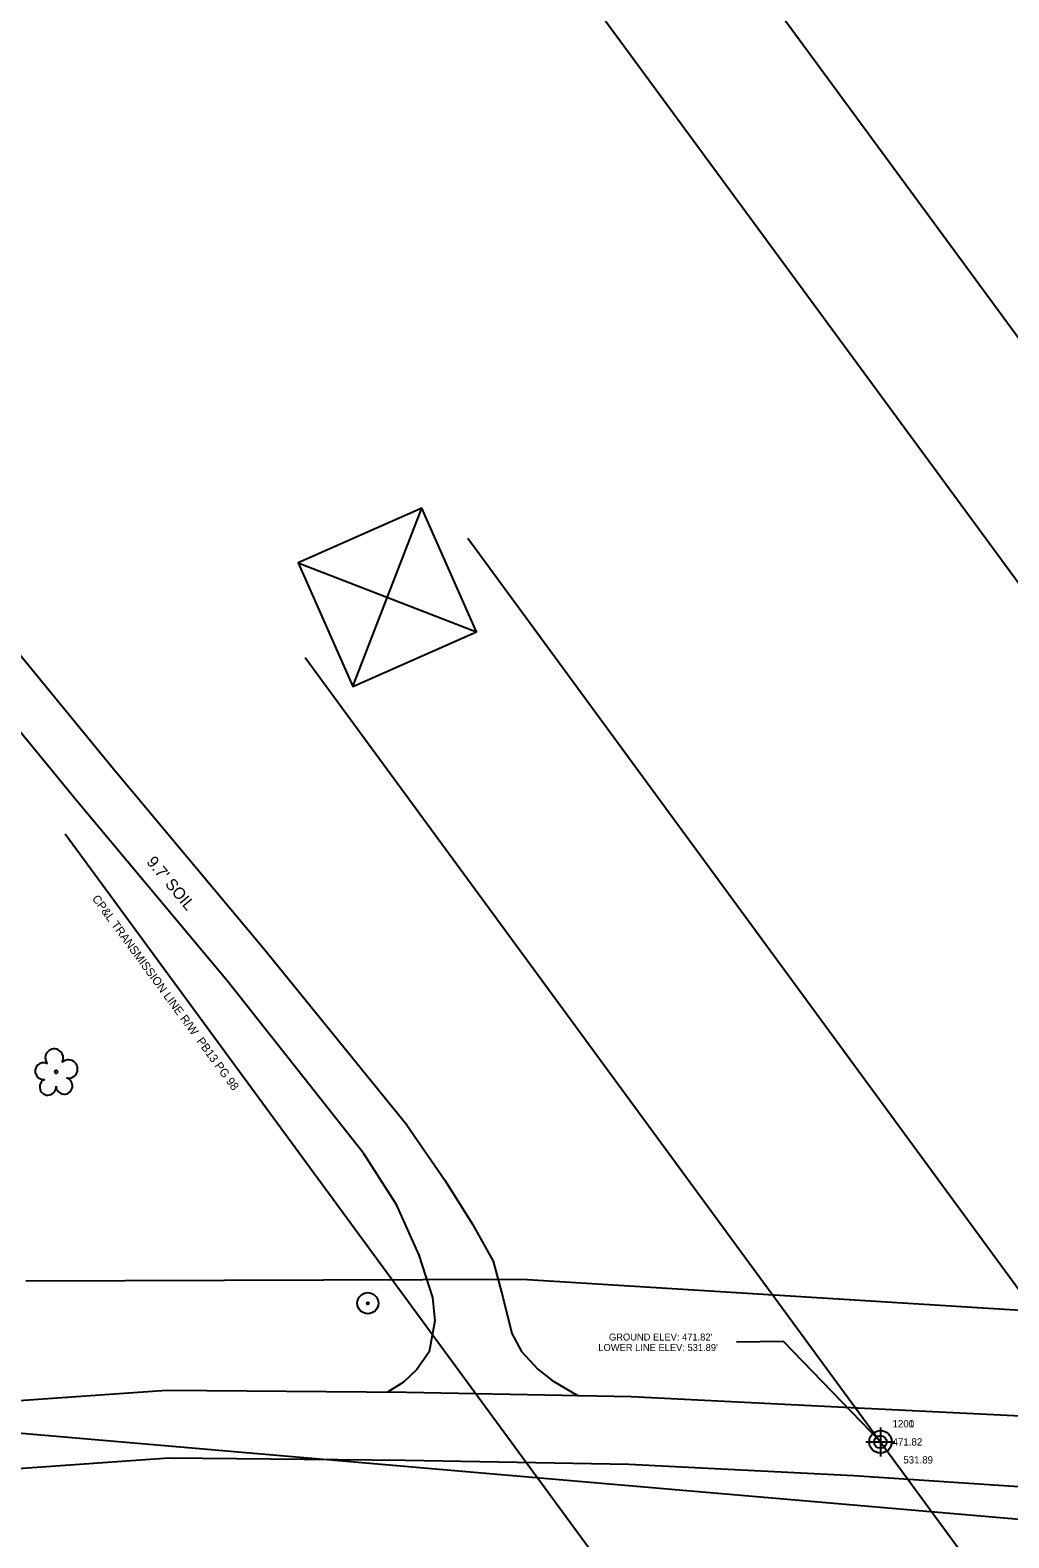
# Model space of a CAD drawing. Extents: x 2060057 to 2062431, y 911685 to 913703.
# Drawn here: x 2060635.5 to 2060837.6, y 912720.7 to 913031.9 of the extents above; entities that cross this region are included whole.
import ezdxf

# ---------------------------------------------------------------- set-up
doc = ezdxf.new("R2010")
doc.units = 0
for name, color, linetype in [('Cogo Default Point CELL', 7, 'Continuous'), ('COGO Default Point Elevation', 7, 'Continuous'), ('COGO Default Point Number', 7, 'Continuous'), ('Exist Horizontal Baseline Alignment', 7, 'Continuous'), ('Exist Right of Way Line', 7, 'Continuous'), ('Exist Right of Way Line Text', 7, 'Continuous'), ('Exist Roads Soil', 7, 'Continuous'), ('Exist Roads Soil Text', 7, 'Continuous'), ('Exist Utilities Other Located Object CELL', 7, 'Continuous'), ('Exist Utilities Other Located Object Leader', 7, 'Continuous'), ('Exist Utilities Other Located Object Text', 7, 'Continuous'), ('Exist Utilities Power Tower CELL', 7, 'Continuous'), ('Exist Utilities Power UG Cable', 7, 'Continuous'), ('Exist Vegetation Tree CELL', 7, 'Continuous')]:
    doc.layers.add(name, color=color, linetype=linetype)

# ---------------------------------------------------------------- blocks, each defined once
blk = doc.blocks.new('EXIST UTILITIES OTHER LOCATED OBJECT')
at = {"layer": 'Exist Utilities Other Located Object CELL'}
for radius in [0.0436, 0.0048]:
    blk.add_circle((0, 0), radius, dxfattribs=at)
blk = doc.blocks.new('EXIST VEGETATION TREE')
at = {"layer": 'Exist Vegetation Tree CELL'}
blk.add_line((0, 0), (0, 0), dxfattribs=at)
blk.add_circle((0, 0), 0.00652, dxfattribs=at)
for centre, radius, start, end in [((-0.0077, 0.0575), 0.0371, 330.16508, 219.71335), ((-0.0521, 0.0031), 0.0345, 62.66361, 279.3457), ((0.051, 0.0118), 0.038, 257.1011, 134.19993), ((-0.0341, -0.0624), 0.0338, 111.56708, 6.23104), ((0.0335, -0.058), 0.034, 181.28216, 74.55999)]:
    blk.add_arc(centre, radius, start, end, dxfattribs=at)

msp = doc.modelspace()

# ---------------------------------------------------------------- linework, layer by layer
at = {"layer": 'Cogo Default Point CELL'}
for points in [[(2060811.07, 912743.46), (2060811.07, 912740.46)], [(2060811.07, 912743.46), (2060811.07, 912740.46)], [(2060808.07, 912740.46), (2060811.07, 912740.46)], [(2060808.07, 912740.46), (2060811.07, 912740.46)], [(2060811.07, 912740.46), (2060814.07, 912740.46)], [(2060811.07, 912740.46), (2060811.07, 912737.46)], [(2060811.07, 912740.46), (2060814.07, 912740.46)], [(2060811.07, 912740.46), (2060811.07, 912737.46)]]:
    msp.add_lwpolyline(points, dxfattribs=at)
msp.add_circle((2060811.07, 912740.46), 2.34, dxfattribs=at)
msp.add_circle((2060811.07, 912740.46), 2.34, dxfattribs=at)
at = {"layer": 'Exist Horizontal Baseline Alignment'}
msp.add_lwpolyline([(2060519.43, 912752.09), (2061230.37, 912690.89), (2061909.97, 912640.52)], dxfattribs=at)
at = {"layer": 'Exist Right of Way Line'}
for p, q in [((2060737.08, 912774.01), (2060634.59, 912773.61)), ((2060840, 912767.59), (2060737.08, 912774.01))]:
    msp.add_line(p, q, dxfattribs=at)
msp.add_lwpolyline([(2060642.71, 912865.98), (2061240.84, 912050.99)], dxfattribs=at)
at = {"layer": 'Exist Roads Soil'}
for points in [[(2060713.36, 912805.74), (2060683.97, 912841.93), (2060652.7, 912879.29), (2060619.5, 912919.71), (2060595.31, 912948.3), (2060581.6, 912964.35), (2060565.45, 912981.01), (2060558.75, 912988.23)], [(2060704.23, 912800.14), (2060676.24, 912835.58), (2060645, 912872.9), (2060611.82, 912913.31), (2060587.69, 912941.82), (2060574.2, 912957.62), (2060558.36, 912973.95), (2060550.71, 912981.07)], [(2060713.36, 912805.74), (2060721.1, 912794.45), (2060726.86, 912785.4), (2060731.09, 912777.77), (2060733.12, 912770.33), (2060734.96, 912762.81), (2060736.97, 912759.12), (2060740.31, 912755.47), (2060743.25, 912753.1), (2060748.64, 912749.97)], [(2060704.23, 912800.14), (2060710.97, 912789.6), (2060715.76, 912779.02), (2060718.57, 912770.26), (2060719.08, 912765.43), (2060717.86, 912759.04), (2060715.33, 912755.38), (2060712.61, 912752.78), (2060709.25, 912750.69)], [(2060886.37, 912743.53), (2060806.37, 912747.43), (2060759.57, 912749.76), (2060713.19, 912750.65), (2060663.71, 912751.08), (2060616.38, 912747.76), (2060575.1, 912744.6), (2060543.35, 912739.77), (2060504.43, 912731.49), (2060468.26, 912721.59), (2060424.39, 912707.77), (2060377.41, 912691.43), (2060338.24, 912674.94), (2060295.3, 912655.88), (2060238.54, 912626.65), (2060196.31, 912601.76), (2060161.36, 912579.41)], [(2060883.98, 912728.25), (2060805.57, 912733.45), (2060759.09, 912735.76), (2060713, 912736.65), (2060664.14, 912737.07), (2060617.4, 912733.8), (2060576.69, 912730.68), (2060545.86, 912726), (2060507.74, 912717.88), (2060472.21, 912708.15), (2060428.79, 912694.48), (2060382.44, 912678.35), (2060343.79, 912662.09), (2060301.35, 912643.25), (2060245.31, 912614.39), (2060203.64, 912589.83), (2060168.91, 912567.61)]]:
    msp.add_lwpolyline(points, dxfattribs=at)
at = {"layer": 'Exist Utilities Other Located Object Leader'}
msp.add_lwpolyline([(2060811.07, 912740.46), (2060791.02, 912761.16), (2060781.36, 912761.02)], dxfattribs=at)
at = {"layer": 'Exist Utilities Power Tower CELL'}
msp.add_lwpolyline([(2060702.09, 912896.38), (2060727.64, 912907.66), (2060716.36, 912933.21), (2060690.81, 912921.93), (2060702.09, 912896.38), (2060716.36, 912933.21), (2060690.81, 912921.93), (2060727.64, 912907.66)], dxfattribs=at)
at = {"layer": 'Exist Utilities Power UG Cable'}
for points in [[(2060304.19, 913696.4), (2061127.5, 912576.77)], [(2060280.08, 913678.67), (2061103.4, 912559.04)], [(2060725.83, 912927), (2061324.02, 912111.8)], [(2060692.26, 912902.37), (2061290.45, 912087.17)]]:
    msp.add_lwpolyline(points, dxfattribs=at)

# ---------------------------------------------------------------- block references
at = {"layer": 'Exist Utilities Other Located Object CELL'}
for p, xscale, yscale in [((2060705.21, 912769.08), 50, 50), ((2060811.07, 912740.46), 30, 30)]:
    msp.add_blockref('EXIST UTILITIES OTHER LOCATED OBJECT', p, dxfattribs=dict(at, xscale=xscale, yscale=yscale))
at = {"layer": 'Exist Vegetation Tree CELL', "xscale": 50, "yscale": 50}
msp.add_blockref('EXIST VEGETATION TREE', (2060640.84, 912816.84), dxfattribs=at)

# ---------------------------------------------------------------- texts
at = {"layer": 'COGO Default Point Elevation'}
for s, p in [('471.82', (2060813.57, 912739.71)), ('531.89', (2060815.79, 912736))]:
    msp.add_text(s, height=1.5, dxfattribs=at).set_placement(p)
at = {"layer": 'COGO Default Point Number'}
for s in ['1200', '1201']:
    msp.add_text(s, height=1.5, dxfattribs=at).set_placement((2060813.57, 912743.46))
at = {"layer": 'Exist Right of Way Line Text'}
msp.add_text('CP&L TRANSMISSION LINE R/W  PB13 PG 98', height=1.728, rotation=306.275, dxfattribs=at).set_placement((2060648.17, 912852.56))
at = {"layer": 'Exist Roads Soil Text'}
msp.add_text("9.7' SOIL", height=2.4, rotation=309.9288, dxfattribs=at).set_placement((2060659.36, 912860.11))
at = {"layer": 'Exist Utilities Other Located Object Text'}
for s, p in [("GROUND ELEV: 471.82'", (2060755.01, 912761.38)), ("LOWER LINE ELEV: 531.89'", (2060752.82, 912759.22))]:
    msp.add_text(s, height=1.44, dxfattribs=at).set_placement(p)

doc.saveas('drawing.dxf')
